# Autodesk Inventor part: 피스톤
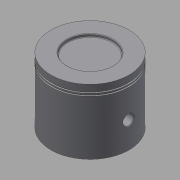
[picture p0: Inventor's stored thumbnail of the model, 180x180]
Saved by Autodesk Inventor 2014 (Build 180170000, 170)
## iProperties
Created: 2016-11
Part Number: 피스톤
Material: 강철, 탄소
Document SubType Name: Modeling
Designer: mduedu
Density: 7.87 g/cm^3
Mass: 410.154 g
Surface Area: 237.492 cm^2
Volume: 52.1161 cm^3
Appearance: 기본값
Author: mduedu
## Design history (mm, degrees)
sketch "스케치1"
  geometry: C1 r 30 at (0, 0); 1 further point
  constraints: 1 centre point, 1 coincident
  dimensions: "d0" = 60 diameter of C1
extrude "돌출1" new body sketch "스케치1" distance "d1" = 50; taper "d2" = 0 deg
sketch "스케치2"
  geometry: C1 r 28 at (0, 0); 1 further point
  constraints: 1 centre point, 1 coincident
  dimensions: "d3" = 56 diameter of C1
extrude "돌출2" cut sketch "스케치2" distance "d4" = 45; taper "d5" = 0 deg
sketch "스케치3"
  geometry: L1 (30, 0)-(30, 50) reference; L2 (30, 45)-(29, 45); L3 (29, 45)-(29, 44); L4 (29, 44)-(30, 44); L5 (30, 44)-(30, 45); L6 (30, 43)-(29, 43); L7 (29, 43)-(29, 42); L8 (29, 42)-(30, 42); L9 (30, 42)-(30, 43); L10 (30, 50)-(-30, 50) reference; L11 (0, 50)-(0, 0)
  constraints: 18 end point, 4 parallel, 3 equal length, 3 perpendicular, 2 horizontal, 2 point on line, 1 midpoint
  dimensions: "d6" = 1 distance of L2.start L2.end; "d8" = 5 distance between parallel lines of L10 L2; "d9" = 1 distance between parallel lines of L6 L4
revolve "회전1" sketch "스케치3" stored, may be unused: angle "d10" = 90 deg
node "작업 평면1"
sketch "스케치4"
  geometry: L1 (0, -22.978)-(45, -22.978) reference; L2 (45, -22.978)-(45, 22.978) reference; L3 (45, 22.978)-(0, 22.978) reference; L4 (0, 22.978)-(0, 25.377) reference; L5 (0, 25.377)-(42, 25.377) reference; L6 (42, 25.377)-(42, 24.187) reference; L7 (42, 24.187)-(43, 24.187) reference; L8 (43, 24.187)-(43, 25.377) reference; L9 (43, 25.377)-(44, 25.377) reference; L10 (44, 25.377)-(44, 24.187) reference; L11 (44, 24.187)-(45, 24.187) reference; L12 (45, 24.187)-(45, 25.377) reference; L13 (45, 25.377)-(50, 25.377) reference; L14 (50, 25.377)-(50, -25.377) reference; L15 (50, -25.377)-(45, -25.377) reference; L16 (45, -25.377)-(45, -24.187) reference; L17 (45, -24.187)-(44, -24.187) reference; L18 (44, -24.187)-(44, -25.377) reference; L19 (44, -25.377)-(43, -25.377) reference; L20 (43, -25.377)-(43, -24.187) reference; L21 (43, -24.187)-(42, -24.187) reference; L22 (42, -24.187)-(42, -25.377) reference; L23 (42, -25.377)-(0, -25.377) reference; L24 (0, -25.377)-(0, -22.978) reference; L25 (12.5, 22.978)-(45, 22.978); L26 (45, 22.978)-(45, -22.978); L27 (45, -22.978)-(12.5, -22.978); L28 (12.5, -22.978)-(12.5, 22.978); C1 r 7.5 at (20, 0); C2 r 4 at (20, 0); 1 further point
  constraints: 8 end point, 2 centre point, 2 parallel, 1 coincident, 1 horizontal, 1 horizontal alignment, 1 perpendicular, 1 point on line, 1 tangent
  dimensions: "d12" = 15 diameter of C1; "d13" = 8 diameter of C2; "d14" = 20 distance of point (0, 0) C1.centre
  node "절단 모서리 투영1"
extrude "돌출3" join sketch "스케치4" stored distance "d15" = 11.75; taper "d16" = 0 deg
extrude "돌출4" cut sketch "스케치4" stored distance "d17" = 72; taper "d18" = 0 deg
fillet "모깎기2" dims "d20" = 3
chamfer "모따기1" distance "d21" = 0.5; stored, may be unused: second distance "d22" = 2, angle "d23" = 45 deg
chamfer "모따기2" distance "d24" = 0.5; stored, may be unused: second distance "d25" = 2, angle "d26" = 45 deg
sketch "스케치5"
  geometry: C1 r 17.5 at (0, 0); 1 further point
  constraints: 1 centre point, 1 coincident
  dimensions: "d27" = 35 diameter of C1
extrude "돌출5" cut sketch "스케치5" distance "d28" = 2; taper "d29" = 0 deg
fillet "모깎기3" dims "d30" = 0.5
node "솔리드1"
mirror "대칭1"
other parameters: "d11" = -16
